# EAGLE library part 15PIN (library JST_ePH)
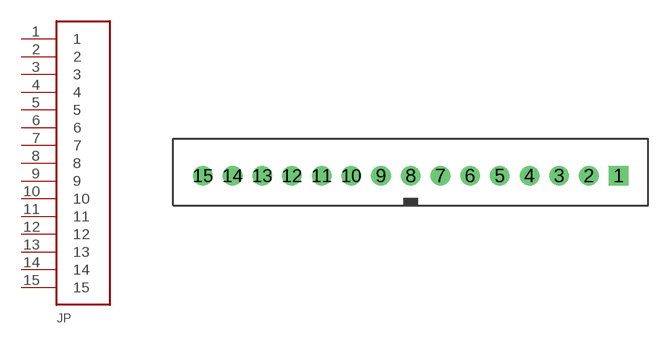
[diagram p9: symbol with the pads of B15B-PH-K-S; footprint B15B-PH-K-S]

Designator prefix JP

## 15PIN  [B15B-PH-K-S]
1  1
2  2
3  3
4  4
5  5
6  6
7  7
8  8
9  9
10  10
11  11
12  12
13  13
14  14
15  15

## Footprint B15B-PH-K-S (pad centres in mm)
drill 0.813 square: 1 14,0
drill 0.813 round: 2 12,0; 3 10,0; 4 8,0; 5 6,0; 6 4,0; 7 2,0; 8 0,0; 9 -2,0; 10 -4,0; 11 -6,0; 12 -8,0; 13 -10,0; 14 -12,0; 15 -14,0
